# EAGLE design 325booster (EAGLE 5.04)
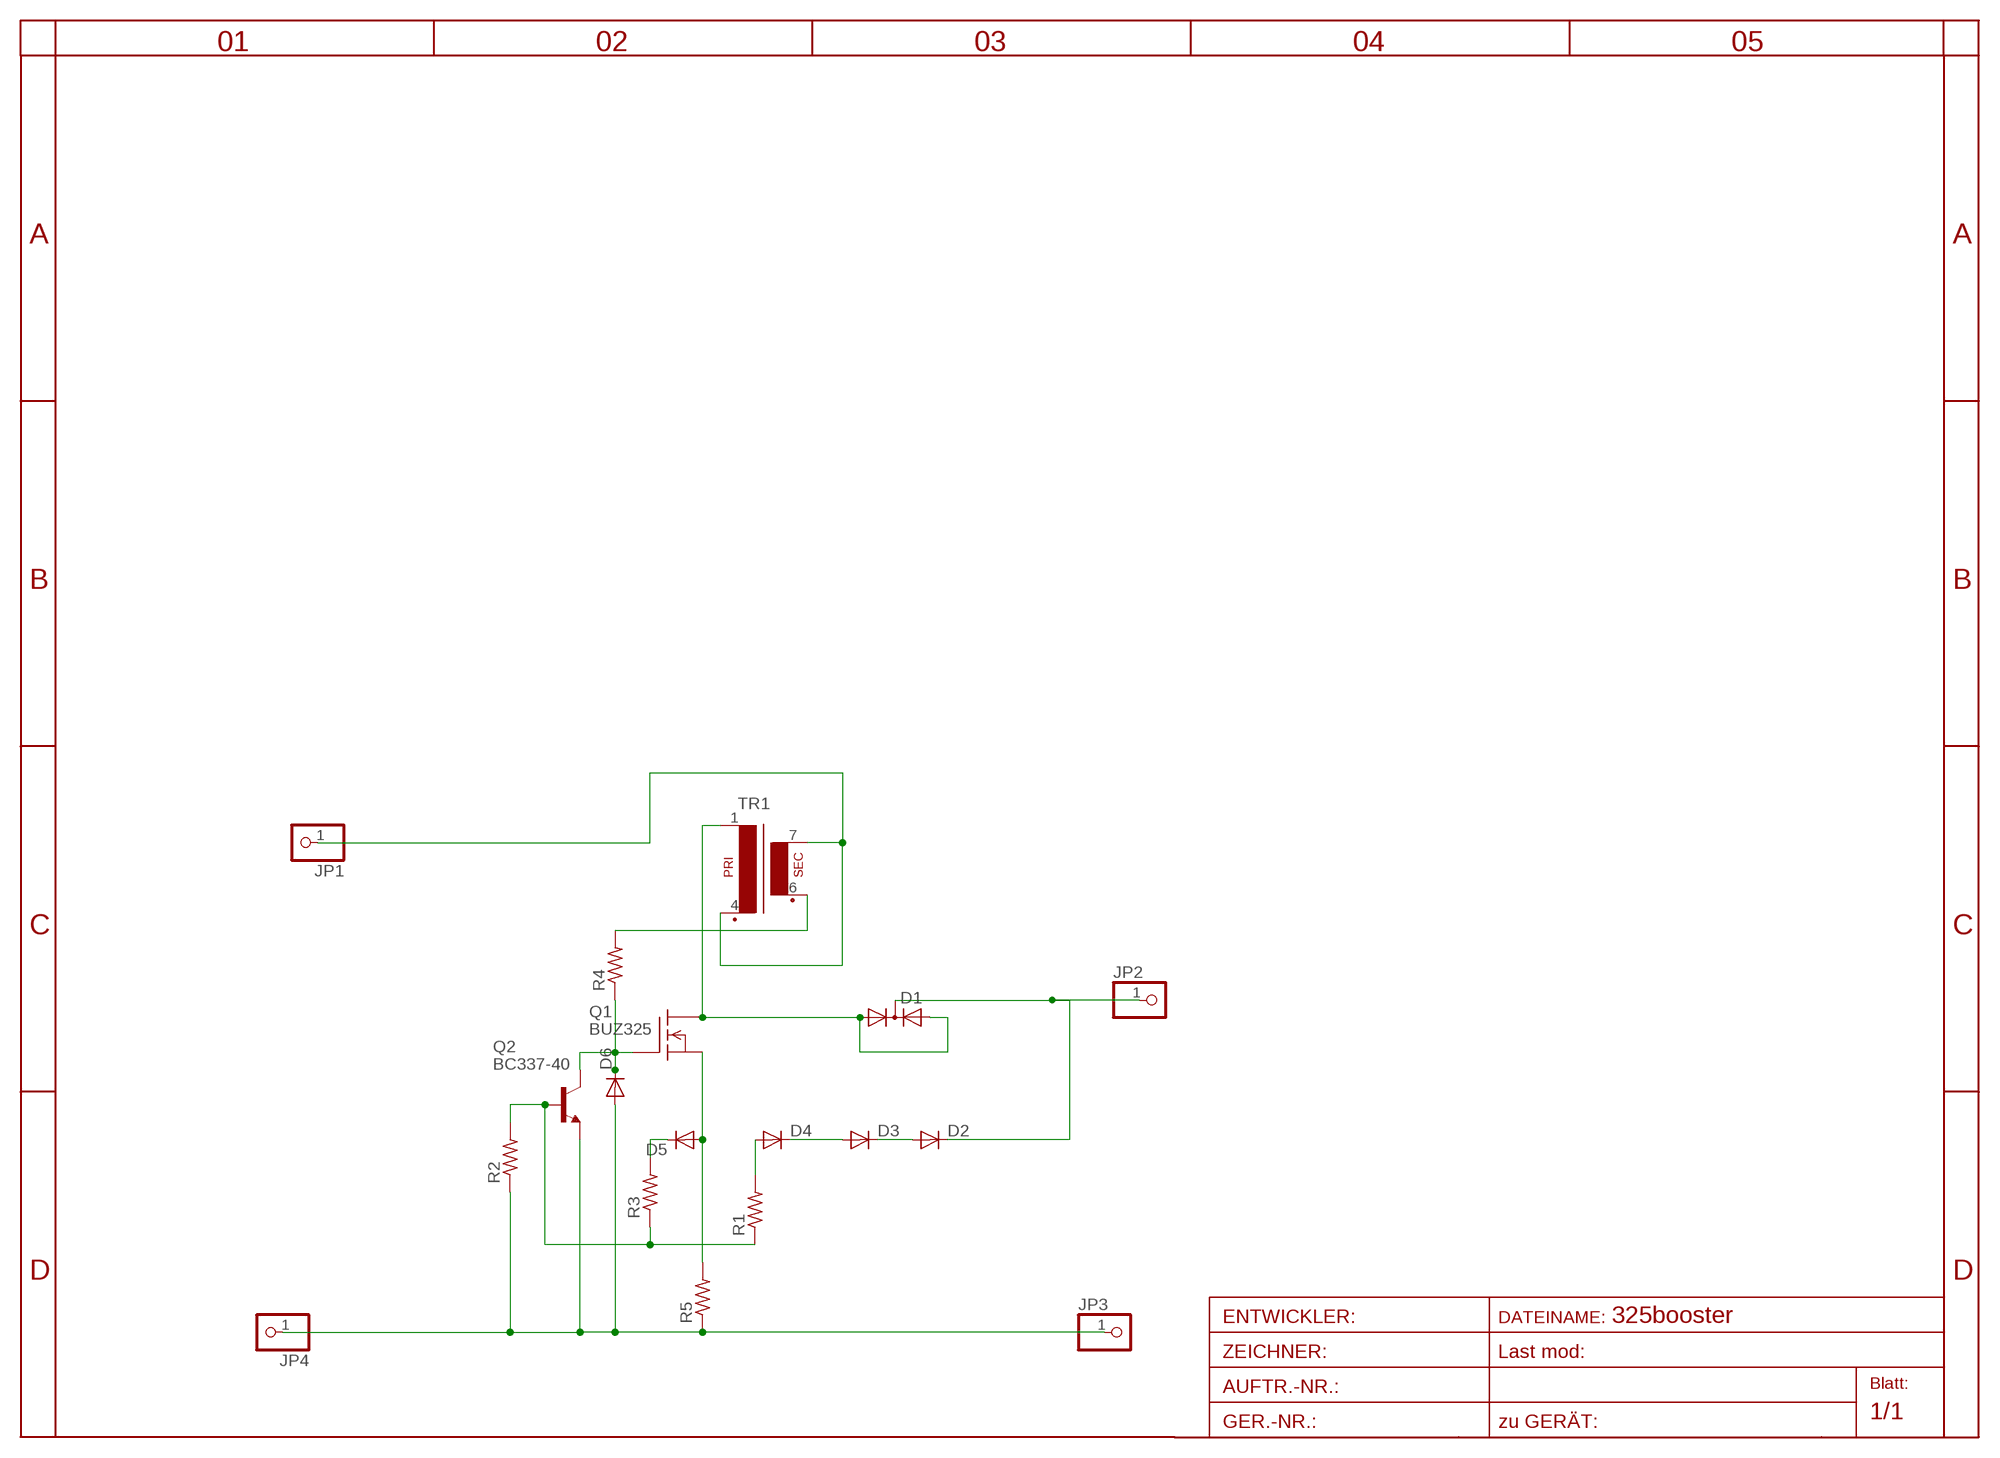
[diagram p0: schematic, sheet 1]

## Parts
D1  DIODE-2AC|CAIW220V  [IW220ABS]
D2  DIODE-DO41-10  [DO41-10]
D3  DIODE-DO41-10  [DO41-10]
D4  DIODE-DO41-10  [DO41-10]
D5  DIODE-DO41-10  [DO41-10]
D6  DIODE-DO41-10  [DO41-10]
JP1  PINHD-1X1  [1X01]
JP2  PINHD-1X1  [1X01]
JP3  PINHD-1X1  [1X01]
JP4  PINHD-1X1  [1X01]
Q1  BUZ325  [TO218]
Q2  BC337-40  [TO92]
R1  R-US_0204/7  [0204/7]
R2  R-US_0204/7  [0204/7]
R3  R-US_0204/7  [0204/7]
R4  R-US_0204/7  [0204/7]
R5  R-US_0204/7  [0204/7]
TR1  EE20-1  [EE20-1]

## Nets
BASE: Q2.2(B) R1.1 R2.2 R3.1
DRAIN: D1.A1 D1.A2 Q1.2(D) TR1.1
GATE: D6.C Q1.1(G) Q2.3(C) R4.1
LSPERR: R4.2 TR1.6(S3)
N$3: D2.A D3.C
N$4: D3.A D4.C
N$5: D4.A R1.2
N$10: D5.C R3.2
N$13: JP1.1 TR1.4(P2) TR1.7(S4)
SOURCE: D5.A Q1.3(S) R5.2
V+OUT: D1.C D2.C JP2.1
V-: D6.A JP3.1 JP4.1 Q2.1(E) R2.1 R5.1

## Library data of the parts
D1 = diode-1:DIODE-2AC|CA: Dual DIODE Anode-Cathode|Cathode-Anode
D2-D6 = diode-1:DIODE-: DIODE
JP1-JP4 = pinhead:PINHD-1X1: PIN HEADER
Q1 = transistor-fet:BUZ325: N-Channel Enhancement MOSFET 400V; 10,5A; 0,5Ohm
Q2 = transistor-npn:BC337*: NPN Transistor
R1-R5 = rcl-2:R-US_: RESISTOR, American symbol
TR1 = trafo:EE20-1: TRANSFORMER 1 primary winding, 1 secondary winding ERA

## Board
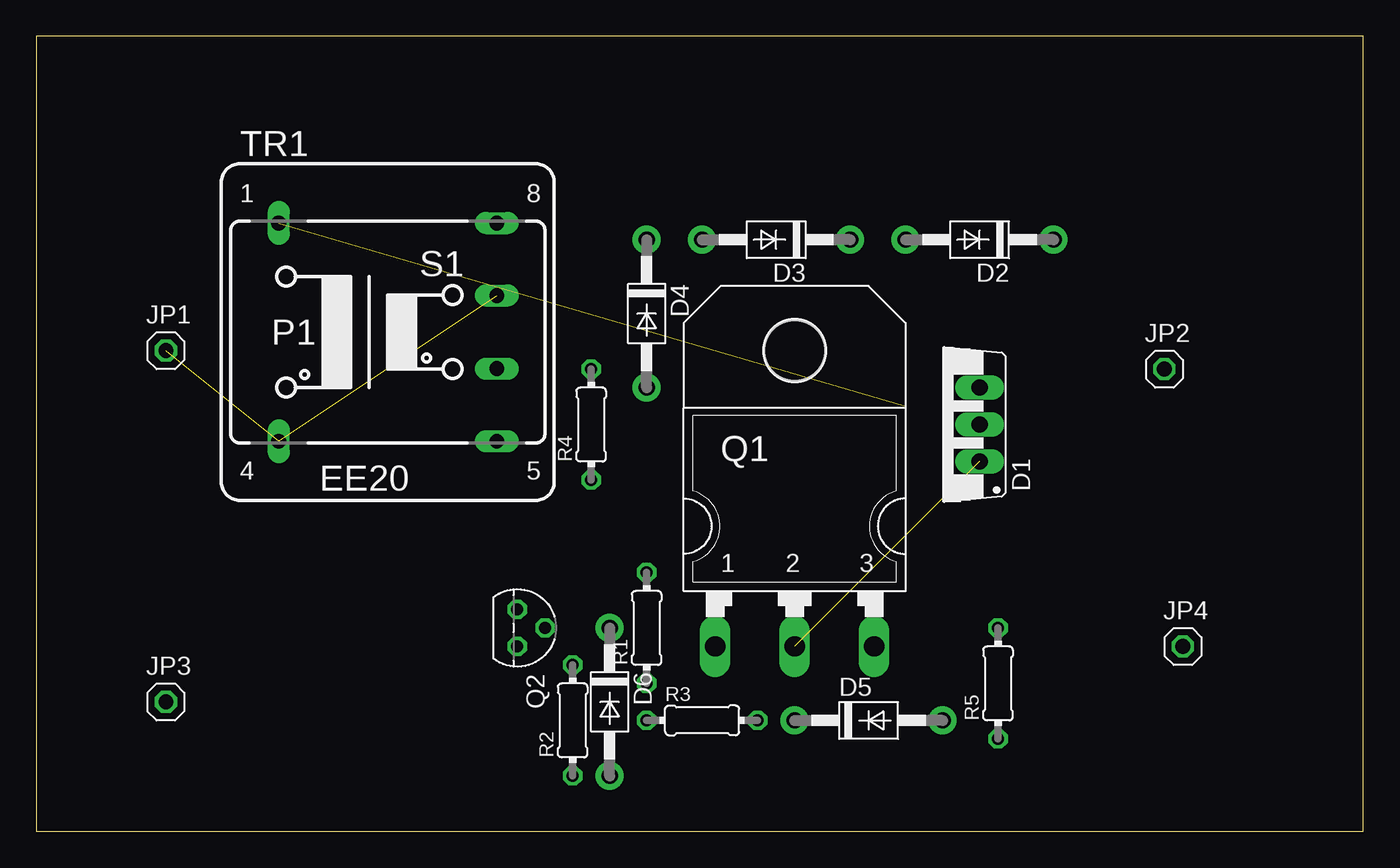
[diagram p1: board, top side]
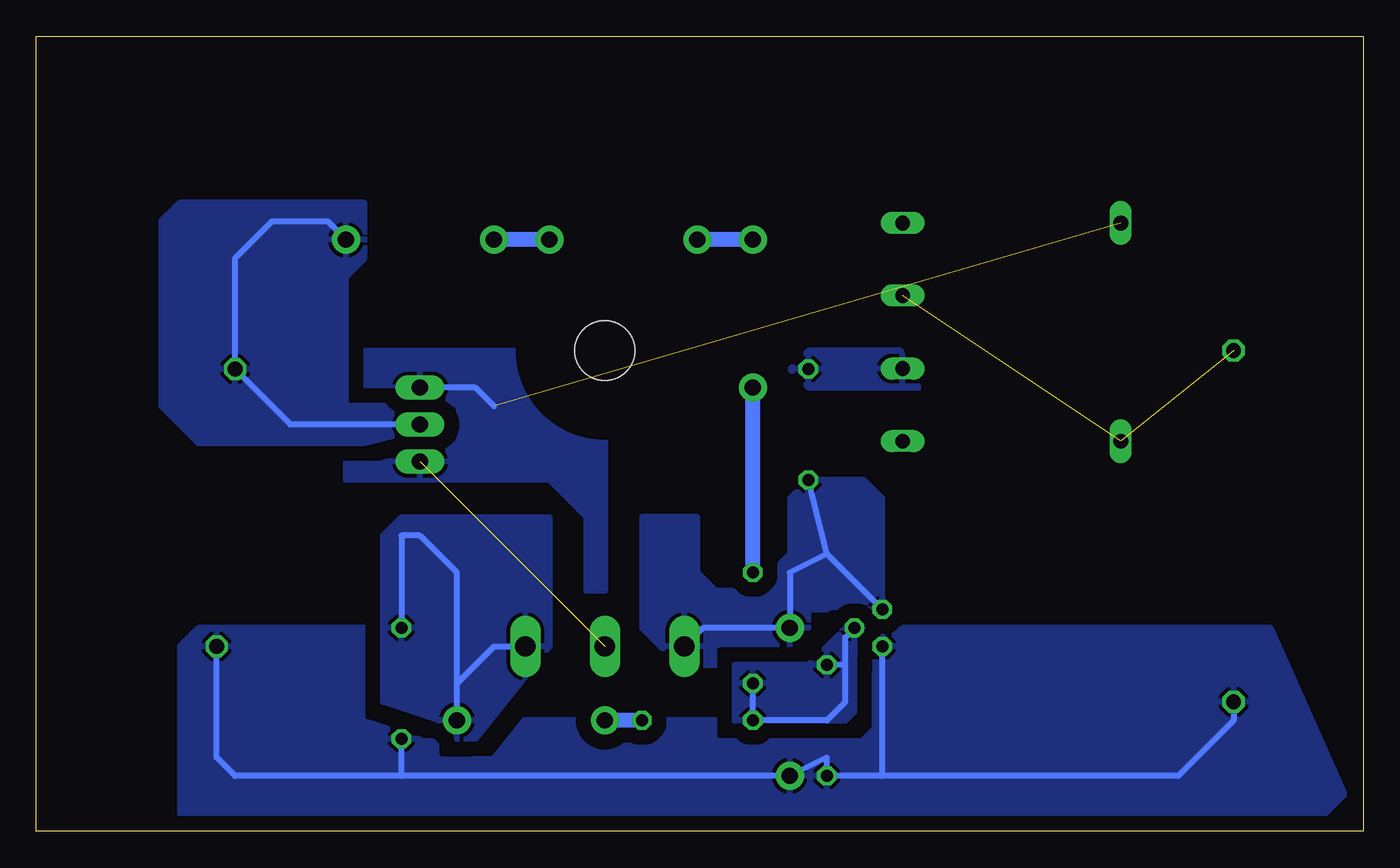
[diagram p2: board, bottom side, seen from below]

Size 91.11 x 54.6 mm. Coordinates in mm from the lower left corner, seen from the top.
Outline: 0,0 91.11,0 91.11,54.6 0,54.6 0,0
Copper layers (1*16): Top 0.035mm / dielectric 1.5mm / Bottom 0.035mm
Design rules "default": minimum track width 10mil, minimum drill 24mil, track to track 8mil, track to pad 8mil, pad to pad 8mil, via to via 8mil, smd to smd 8mil, copper to edge 40mil, drill to drill 8mil, minimum pad ring 10mil, minimum via ring 8mil, stop-mask expansion 4mil, vias tented up to drill 0mil, thermal gap 10mil

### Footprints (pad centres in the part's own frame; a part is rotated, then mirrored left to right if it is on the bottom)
IW220ABS = drill 1.118 long: A1 -2.54,-2.54; A2 2.54,-2.54; C 0,-2.54
DO41-10 = drill 1.118 pad 1.93 round: A 5.08,0; C -5.08,0
1X01 = drill 1.016 octagon: 1 0,0
TO218 = drill 1.397 long: 1 -5.461,-10.16; 2 0,-10.16; 3 5.461,-10.16 | hole 4.115: 0,10.16
TO92 = drill 0.813 octagon: 1 1.27,0; 2 0,1.905; 3 -1.27,0
0204/7 = drill 0.813 octagon: 1 -3.81,0; 2 3.81,0
EE20-1 = drill 1.016 long: 1 -7.493,7.493; 4 -7.493,-7.493; 5 7.493,-7.493; 6 7.493,-2.515; 7 7.493,2.515; 8 7.493,7.493

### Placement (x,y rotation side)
D1  62.23,27.94 90 top
D2  64.77,40.64 180 top
D3  50.8,40.64 180 top
D4  41.91,35.56 270 top
D5  57.15,7.62 0 top
D6  39.37,8.89 270 top
JP1  8.89,33.02 0 top
JP2  77.47,31.75 0 top
JP3  8.89,8.89 0 top
JP4  78.74,12.7 0 top
Q1  52.07,22.86 0 top
Q2  33.02,13.97 270 top
R1  41.91,13.97 90 top
R2  36.83,7.62 90 top
R3  45.72,7.62 0 top
R4  38.1,27.94 90 top
R5  66.04,10.16 90 top
TR1  24.13,34.29 0 top

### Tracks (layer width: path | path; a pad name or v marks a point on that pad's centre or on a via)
BASE
  Bottom 0.406: 35.56,11.43 35.56,8.89 36.83,7.62 R3.1 R1.1 | 35.56,11.43 35.56,13.34 Q2.2 | 35.56,11.43 R2.2
  pour Bottom (isolate 1.016, rank 3): 34.29,13.97 35.56,13.97 38.1,11.43 43.18,11.43 43.18,7.62 35.56,7.62 34.92,8.26 34.92,12.06 34.29,12.7
DRAIN  (2 unrouted)
  Bottom 0.406: D1.A2 60.96,30.48 59.69,29.21
  pour Bottom (isolate 1.016, rank 4): 69.85,33.02 55.88,33.02 52.07,27.94 52.07,16.51 53.34,16.51 53.34,21.59 55.88,24.13 69.85,24.13
GATE
  Bottom 0.406: Q2.3 36.83,19.05 | 36.83,19.05 R4.1 | 36.83,19.05 39.37,17.78 D6.C 45.34,13.97 Q1.1
  pour Bottom (isolate 1.016, rank 4): 49.53,21.59 49.53,13.97 46.99,11.43 39.37,11.43 38.1,12.7 38.1,15.24 33.02,15.24 33.02,22.86 34.29,24.13 38.1,24.13 39.37,22.86 39.37,19.05 40.64,17.78 40.64,16.51 44.45,16.51 45.72,17.78 45.72,21.59
LSPERR
  pour Bottom (isolate 1.016, rank 4): 31.75,33.02 38.1,33.02 39.37,31.75 38.1,30.48 30.48,30.48
N$3
  Bottom 1.016: D3.C D2.A
N$4
  Bottom 1.016: D4.C D3.A
N$5
  Bottom 1.016: R1.2 D4.A
N$10
  Bottom 1.016: R3.2 D5.C
N$13  (2 unrouted)
SOURCE
  Bottom 0.406: D5.A 62.23,10.16 | 62.23,10.16 59.69,12.7 Q1.3 | 62.23,10.16 62.23,17.78 64.77,20.32 66.04,20.32 R5.2
  pour Bottom (isolate 1.016, rank 4): 67.31,8.89 67.31,20.32 66.04,21.59 55.88,21.59 55.88,12.7 60.96,6.35 62.23,6.35 63.5,7.62
V+OUT
  Bottom 0.406: D1.C 73.66,27.94 JP2.1 77.47,39.37 74.93,41.91 71.12,41.91 D2.C
  pour Bottom (isolate 1.016, rank 3): 63.5,27.94 64.77,29.21 69.85,29.21 69.85,38.1 68.58,39.37 68.58,43.18 81.28,43.18 82.55,41.91 82.55,29.21 80.01,26.67 68.58,26.67
V-
  Bottom 0.406: JP3.1 8.89,7.62 12.7,3.81 33.02,3.81 | 33.02,3.81 R2.1 36.83,5.08 D6.A 66.04,3.81 | JP4.1 78.74,5.08 77.47,3.81 66.04,3.81 | 33.02,3.81 Q2.1 | 66.04,3.81 R5.1
  pour Bottom (isolate 1.016, rank 5): 6.35,13.97 33.02,13.97 36.83,10.16 36.83,7.62 68.58,7.62 68.58,13.97 80.01,13.97 81.28,12.7 81.28,1.27 2.54,1.27 1.27,2.54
